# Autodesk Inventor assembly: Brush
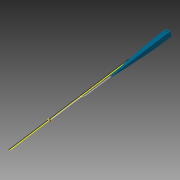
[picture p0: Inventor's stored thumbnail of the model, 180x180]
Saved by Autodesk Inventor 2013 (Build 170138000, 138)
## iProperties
Created: 2006-04
Part Number: Brush
Document SubType Name: Assembly
Designer: Autodesk, Inc.
Mass: 143.512 g
Surface Area: 423.543 cm^2
Volume: 24.3841 cm^3
Density: 5.88547 g/cm^3
Author: Autodesk, Inc.
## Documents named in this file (4)
- C:\Users\boganb\Documents\B2 Design\Goodyear\2013 Tutorial Files\Dynamic Simulation 4\Components\Brush.iam
- C:\Users\boganb\Documents\B2 Design\Goodyear\2013 Tutorial Files\Dynamic Simulation 4\Components\Arm.ipt
- C:\Users\boganb\Documents\B2 Design\Goodyear\2013 Tutorial Files\Dynamic Simulation 4\Components\Wiper.ipt
- C:\Users\boganb\Documents\B2 Design\Goodyear\2013 Tutorial Files\Dynamic Simulation 4\Components\Brush.ipt
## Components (3 placed, 3 different names)
1. Arm:1
2. Wiper:1
3. Brush:1
